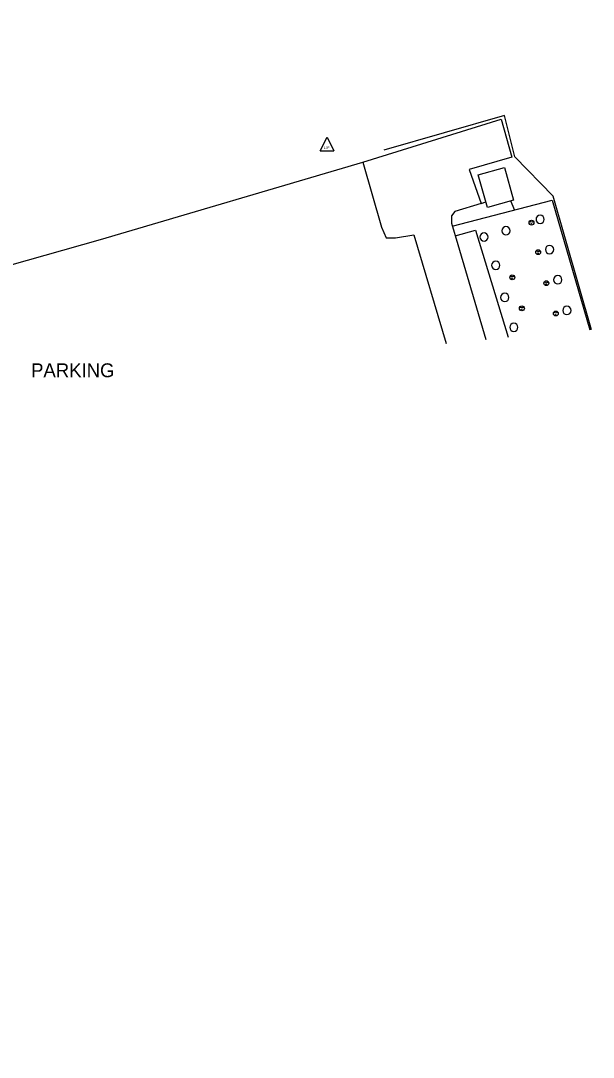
# Model space of a CAD drawing. Extents: x 1901471 to 1963503, y 756461 to 799997.
# Drawn here: x 1911515.7 to 1911722.2, y 760648.5 to 761022.6 of the extents above; entities that cross this region are included whole.
import ezdxf

# ---------------------------------------------------------------- set-up
doc = ezdxf.new("R2010")
doc.units = 0
for name, color, linetype in [('Default', 7, 'Continuous'), ('RD_EX_Bldg', 7, 'Continuous'), ('RD_EX_Conc', 7, 'Continuous'), ('RD_EX_DR_Inlet', 7, 'Continuous'), ('RD_EX_Driveway', 7, 'Continuous'), ('RD_EX_Fence_Other', 7, 'Continuous'), ('RD_EX_Road', 7, 'Continuous'), ('RD_EX_UT', 7, 'Continuous'), ('RD_HC_Cl', 7, 'Continuous')]:
    doc.layers.add(name, color=color, linetype=linetype)

# ---------------------------------------------------------------- blocks, each defined once
blk = doc.blocks.new('MH')
at = {"layer": 'RD_EX_DR_Inlet'}
for centre, radius in [((2.8124998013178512e-05, 6.249999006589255e-06), 1.7500000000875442), ((-0.6646802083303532, 0.6297874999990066), 0.1750000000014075), ((0.5597729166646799, 0.55982395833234), 0.1750000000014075), ((-0.08743541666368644, -0.6647020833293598), 0.1750000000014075)]:
    blk.add_circle(centre, radius, dxfattribs=at)
blk = doc.blocks.new('LP')
at = {"layer": 'RD_EX_UT'}
for p, q in [((-5.000000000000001, -3.724166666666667), (0, 6.275833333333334)), ((0, 6.275833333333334), (5.000000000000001, -3.724166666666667)), ((-5.000000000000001, -3.724166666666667), (5.000000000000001, -3.724166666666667))]:
    blk.add_line(p, q, dxfattribs=at)
blk.add_text('L/P', height=1.9999995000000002, dxfattribs=at).set_placement((-2.397166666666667, -2.44275))
blk = doc.blocks.new('RD_EX_SU_Gas')
at = {"layer": 'Default'}
for centre, start, end in [((7.776250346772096e-18, 0), 90.00000000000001, 270), ((-7.776250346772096e-18, 0), 270, 90)]:
    blk.add_arc(centre, 0.12700000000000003, start, end, dxfattribs=at)

msp = doc.modelspace()

# ---------------------------------------------------------------- linework, layer by layer
at = {"layer": 'RD_EX_Bldg'}
msp.add_lwpolyline([(1911684.0500000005, 760955.2600000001), (1911680.7300000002, 760966.9900000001), (1911690.1800000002, 760969.6600000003), (1911693.4900000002, 760957.9300000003)], close=True, dxfattribs=at)
at = {"layer": 'RD_EX_Conc'}
for points in [[(1911671.3800000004, 760948.5000000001), (1911707.3800000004, 760957.9000000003), (1911721.0400000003, 760911.05)], [(1911681.7700000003, 760956.6300000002), (1911683.5000000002, 760957.2100000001)], [(1911693.7800000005, 760954.3500000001), (1911692.5500000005, 760957.6700000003)], [(1911672.4500000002, 760945.0300000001), (1911679.7700000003, 760947.1000000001), (1911691.4800000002, 760908.3800000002)]]:
    msp.add_lwpolyline(points, dxfattribs=at)
at = {"layer": 'RD_EX_Driveway'}
msp.add_lwpolyline([(1911639.1500000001, 760971.58), (1911689.0300000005, 760987.1400000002), (1911692.8500000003, 760973.3400000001), (1911677.4100000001, 760968.9800000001), (1911681.7700000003, 760956.6300000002), (1911672.3300000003, 760953.7300000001), (1911671.0500000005, 760952.2700000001), (1911671.0500000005, 760949.55), (1911673.4200000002, 760941.9200000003), (1911683.5200000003, 760907.57)], dxfattribs=at)
at = {"layer": 'RD_EX_Fence_Other'}
for points in [[(1911721.6300000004, 760911.0900000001), (1911707.7700000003, 760959.2600000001), (1911693.9100000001, 760973.5200000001), (1911690.1800000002, 760988.4500000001), (1911646.7200000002, 760975.9200000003)], [(1911649.2500000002, 760976.6500000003), (1911646.7200000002, 760975.9200000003)], [(1911649.2500000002, 760976.6500000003), (1911646.7200000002, 760975.9200000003)]]:
    msp.add_lwpolyline(points, dxfattribs=at)
at = {"layer": 'RD_EX_Road'}
msp.add_lwpolyline([(1911298.0700000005, 760854.1400000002), (1911401.7100000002, 760895.5000000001), (1911470.8300000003, 760922.81), (1911544.4000000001, 760943.7200000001), (1911639.1500000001, 760971.58), (1911645.8400000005, 760948.1700000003), (1911647.5100000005, 760944.2700000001), (1911650.8600000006, 760944.2700000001), (1911657.5500000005, 760945.3900000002), (1911669.1300000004, 760906.1000000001)], dxfattribs=at)
at = {"layer": 'RD_HC_Cl'}
for centre, radius, start, end in [((1905408.2458716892, 771170.6492824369), 11414.0664, 290.894469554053, 304.0088245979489), ((1905390.191717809, 771086.470862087), 11384.366000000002, 290.90340658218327, 304.0085286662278), ((1905358.488046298, 771272.4106571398), 11611.5386, 290.90197060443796, 304.0171003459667)]:
    msp.add_arc(centre, radius, start, end, dxfattribs=at)

# ---------------------------------------------------------------- block references
at = {"layer": 'RD_EX_DR_Inlet', "xscale": 0.5039370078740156, "yscale": 0.5039370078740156}
for p in [(1911699.9500000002, 760949.7500000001), (1911702.3500000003, 760939.08), (1911693.0200000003, 760930.0200000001), (1911705.2900000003, 760927.8900000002), (1911696.4900000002, 760918.82), (1911708.7500000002, 760916.9600000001)]:
    msp.add_blockref('MH', p, dxfattribs=at)
at = {"layer": 'RD_EX_UT'}
for name, p, xscale, yscale in [('LP', (1911626.1900000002, 760977.57), 0.4921259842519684, 0.4921259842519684), ('RD_EX_SU_Gas', (1911703.0800000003, 760950.9400000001), 11.811023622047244, 11.811023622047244), ('RD_EX_SU_Gas', (1911682.8200000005, 760944.56), 11.811023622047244, 11.811023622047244), ('RD_EX_SU_Gas', (1911690.7500000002, 760946.83), 11.811023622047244, 11.811023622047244), ('RD_EX_SU_Gas', (1911706.4800000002, 760940.0300000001), 11.811023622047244, 11.811023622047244), ('RD_EX_SU_Gas', (1911687.0700000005, 760934.3600000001), 11.811023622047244, 11.811023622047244), ('RD_EX_SU_Gas', (1911709.4500000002, 760929.1200000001), 11.811023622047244, 11.811023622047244), ('RD_EX_SU_Gas', (1911690.3200000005, 760922.7500000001), 11.811023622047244, 11.811023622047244), ('RD_EX_SU_Gas', (1911712.7100000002, 760918.07), 11.811023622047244, 11.811023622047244), ('RD_EX_SU_Gas', (1911693.5800000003, 760911.9800000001), 11.811023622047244, 11.811023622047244)]:
    msp.add_blockref(name, p, dxfattribs=dict(at, xscale=xscale, yscale=yscale))

# ---------------------------------------------------------------- texts
at = {"layer": 'RD_EX_Road'}
msp.add_text('PARKING', height=5.000000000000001, dxfattribs=at).set_placement((1911519.3800000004, 760893.9600000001))

doc.saveas('drawing.dxf')
